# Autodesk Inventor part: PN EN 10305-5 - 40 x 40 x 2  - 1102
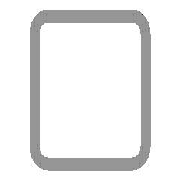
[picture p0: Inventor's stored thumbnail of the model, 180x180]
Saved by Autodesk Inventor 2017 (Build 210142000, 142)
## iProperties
_CCFamilyMember: 26
_CCFamilyDisplayName: PN EN 10305-5 (Rury kwadratowe, spawane, wymiarowane na zimno) - Rury stalowe do zastosowań precyzyjnych -  (Część 5: Rury kwadratowe, spawane, wymiarowane na z
_FrameMemberDoc: Frame Member File
_Version: 15.0.0
_GetPNFromCC: 1
Created: 2016-02
Part Number: PN EN 10305-5 - 40 x 40 x 2  - 1102
Material: Stal, miękka
Description: Rury stalowe do zastosowań precyzyjnych -  (Część 5: Rury kwadratowe, spawane, wymiarowane na zimno)
Document SubType Name: Modeling
Standard: PN
Designer: X
Standards Organization: PN
Language: pl-PL
Size Designation: 40 x 40 x 2
Categories: <MemberInstance><Categories><Category DisplayName="Kształtowniki konstrukcyjne" InternalName="089c4875-fa83-4c05-b084-43b9cc11f5ed" Mnemonic="GRDR"><CategoryPar
Stock Number: 40 x 40 x 2
Density: 7.85 g/cm^3
Appearance: Częściowo polerowana
Mass: 2570.41 g
Surface Area: 3280.35 cm^2
Volume: 327.44 cm^3
IsCustomPart: 1
G_L: 1102,000 mm
G_W: 40,000 mm
G_H: 40,000 mm
Author: X
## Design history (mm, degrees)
node "Płaszczyzna początkowa"
node "Płaszczyzna końcowa"
sketch "Szkic"
  geometry: L1 (-20, -17)-(-20, 17); L2 (-17, 20)-(17, 20); L3 (20, 17)-(20, -17); L4 (17, -20)-(-17, -20); L5 (-17, 18)-(17, 18); L6 (18, 17)-(18, -17); L7 (17, -18)-(-17, -18); L8 (-18, -17)-(-18, 17); L9 (0, 28.87)-(0, -28.87) reference; L10 (-28.87, 0)-(28.87, 0) reference; A1 r 3 centre (-17, -17) between (-20, -17) and (-17, -20); A2 r 3 centre (-17, 17) between (-17, 20) and (-20, 17); A3 r 3 centre (17, 17) between (20, 17) and (17, 20); A4 r 3 centre (17, -17) between (17, -20) and (20, -17); A5 r 1 centre (-17, 17) between (-17, 18) and (-18, 17); A6 r 1 centre (17, 17) between (18, 17) and (17, 18); A7 r 1 centre (17, -17) between (17, -18) and (18, -17); A8 r 1 centre (-17, -17) between (-18, -17) and (-17, -18)
  constraints: 16 end point, 16 point on circle, 8 centre point, 8 tangent, 4 parallel, 3 equal radius, 2 perpendicular, 7 other
  dimensions: "d7" = 3 radius of A1 (= G_IR); "d10" = 40 distance between parallel lines of L2 L4 (= G_H); "d11" = 40 distance between parallel lines of L1 L3 (= G_W); "d12" = 2 distance between parallel lines of L3 L6 (= G_T); "d15" = 20 distance between parallel lines of L2 L10 (= 0.5 x d10); "d16" = 20 distance between parallel lines of L9 L3 (= 0.5 x d11)
extrude "Bryła" new body sketch "Szkic" stored distance "d3" = 1102 (= G_L); taper "d4" = 0 deg
node "Driven Length"
  sketch "Sketch3"
    geometry: L1 (0, 0)-(10, 0) reference
    constraints: 2 end point, 1 horizontal
  workplane "Work Plane3"
  sketch "Sketch4"
    geometry: L1 (-2, 0)-(12, 0) reference; L2 (-2, 1102)-(12, 1102) reference
    dimensions: "d18" = 1102 distance between parallel lines of L1 L2 (derived)
body "Solid1"
other parameters: "G_W" = 40 [user parameter; used in 1 equation term], "G_H" = 40 [user parameter; used in 1 equation term], "G_T" = 2 [user parameter; used in 1 equation term], "G_IR" = 3 [user parameter; used in 1 equation term], "G_L" = 1102 (= d18) [user parameter; used in 1 equation term], "G_OFFSET_START" = 0 [user parameter; used in 1 equation term], "G_OFFSET_END" = -38 [user parameter; used in 1 equation term], "d13" = 0 (computed from G_OFFSET_START), "d14" = 1102 (= G_OFFSET_END + B_L), "d17" = 90 deg
